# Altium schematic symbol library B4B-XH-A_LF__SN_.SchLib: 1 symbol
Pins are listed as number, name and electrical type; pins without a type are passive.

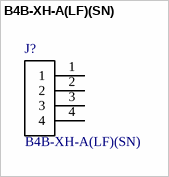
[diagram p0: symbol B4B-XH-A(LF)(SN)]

## B4B-XH-A(LF)(SN)
designator J?
Connector Header Through Hole 4 position 0.098 _2.50mm_; MP: B4B-XH-A_LF__SN_; MF: JST Sales
footprint *JST_B4B-XH-A(LF)(SN)
pins: 1, 2, 3, 4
